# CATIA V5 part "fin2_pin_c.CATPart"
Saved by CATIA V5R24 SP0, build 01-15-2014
Part number: Part5.2
Bounding box of the stored display mesh (mm): x -1.576 to 1.576, y -1.598 to 1.598, z -12 to 0
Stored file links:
  G:\내 드라이브\04_WORK\00_LECTURE\CAD2020\exam\fin2_pin_c.CATPart
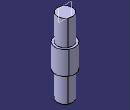
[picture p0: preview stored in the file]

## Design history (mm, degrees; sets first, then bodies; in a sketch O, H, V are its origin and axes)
Body1 (main body)
  Sketch1 on yz-plane, origin (0, 0, 0), H (0, 1, 0), V (0, 0, 1)
    axis line L1 (0, 31.1365) -> (0, -56.5373)
    point P1 (0, 31.1365)
    line L2 (0, 0) -> (-1.25, 0)
    line L3 (-1.25, 0) -> (-1.25, -4.125)
    line L4 (-1.25, -4.125) -> (-1.6, -4.125)
    line L5 (-1.6, -4.125) -> (-1.6, -7.875)
    line L6 (-1.6, -7.875) -> (-1.25, -7.875)
    point P7 (-1.25, -7.875)
    line L7 (-1.25, -7.875) -> (-1.25, -12)
    line L8 (-1.25, -12) -> (0, -12)
    point P9 (0, -12)
    line L9 (0, -12) -> (0, 0)
    length L3 = 4.125
    length L7 = 4.125
    length L9 = 12
    distance L3 L1 = 1.25
    distance L5 L1 = 1.6
    length L5 = 3.75 (reference)
    coincidence: P1 V, P7 L3, P9 L1
    vertical: L1 V, L3 V, L5 V, L7 V, L9 V
    horizontal: L2 H, L4 H, L6 H, L8 H
  Shaft1: profile Sketch1, axis Sketch1.L1, angle 360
